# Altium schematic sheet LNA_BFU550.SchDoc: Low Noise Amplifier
size A4; Author: Almela; Revision: 1.2; SheetNumber: 5; SheetTotal: 7
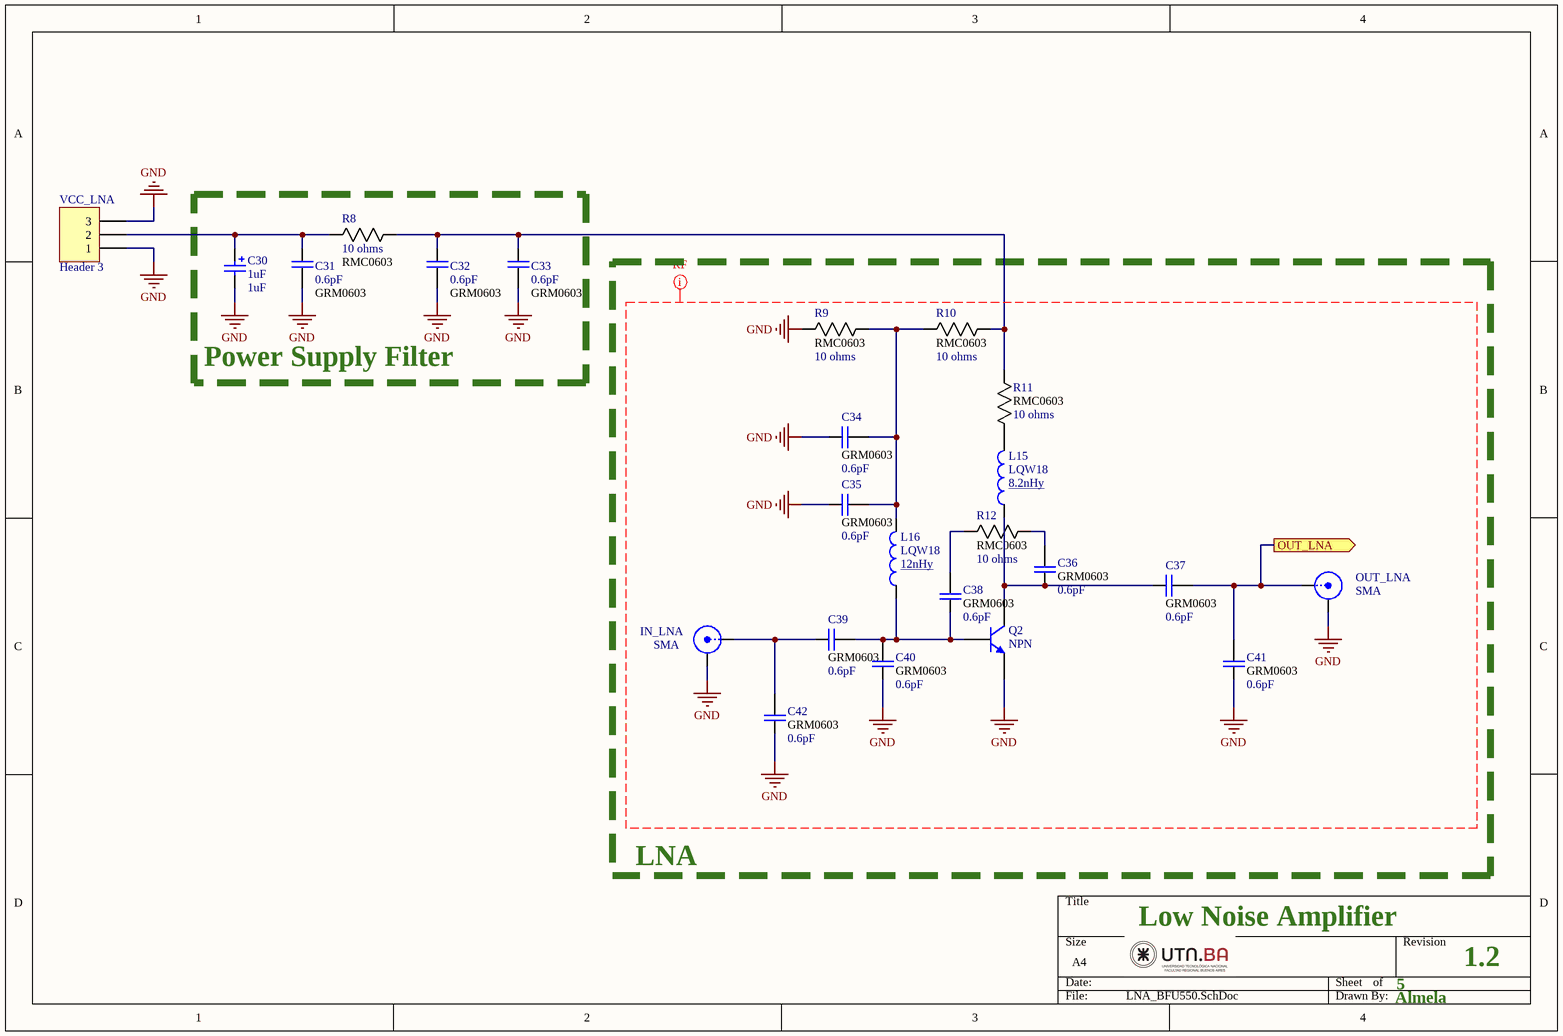
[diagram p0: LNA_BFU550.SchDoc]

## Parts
C30  1uF  [6-0805_N]
C31  value 0.6pF  footprint: GRM0603  [CAPC1608X90N]  (hidden comment: Cap 0603)
C32  value 0.6pF  footprint: GRM0603  [CAPC1608X90N]  (hidden comment: Cap 0603)
C33  value 0.6pF  footprint: GRM0603  [CAPC1608X90N]  (hidden comment: Cap 0603)
C34  value 0.6pF  footprint: GRM0603  [CAPC1608X90N]  (hidden comment: Cap 0603)
C35  value 0.6pF  footprint: GRM0603  [CAPC1608X90N]  (hidden comment: Cap 0603)
C36  value 0.6pF  footprint: GRM0603  [CAPC1608X90N]  (hidden comment: Cap 0603)
C37  value 0.6pF  footprint: GRM0603  [CAPC1608X90N]  (hidden comment: Cap 0603)
C38  value 0.6pF  footprint: GRM0603  [CAPC1608X90N]  (hidden comment: Cap 0603)
C39  value 0.6pF  footprint: GRM0603  [CAPC1608X90N]  (hidden comment: Cap 0603)
C40  value 0.6pF  footprint: GRM0603  [CAPC1608X90N]  (hidden comment: Cap 0603)
C41  value 0.6pF  footprint: GRM0603  [CAPC1608X90N]  (hidden comment: Cap 0603)
C42  value 0.6pF  footprint: GRM0603  [CAPC1608X90N]  (hidden comment: Cap 0603)
IN_LNA  SMA  [SMA-142-0701-851]
L15  LQW18  value 8.2nHy  [INDC1608X100N]
L16  LQW18  value 12nHy  [INDC1608X100N]
OUT_LNA  SMA  [SMA-142-0701-851]
Q2  NPN  [SOT23_N_bfu550a]
R8  value 10 ohms  footprint: RMC0603  [RESC1508X55N]  (hidden comment: Resistor)
R9  value 10 ohms  footprint: RMC0603  [RESC1508X55N]  (hidden comment: Resistor)
R10  value 10 ohms  footprint: RMC0603  [RESC1508X55N]  (hidden comment: Resistor)
R11  value 10 ohms  footprint: RMC0603  [RESC1508X55N]  (hidden comment: Resistor)
R12  value 10 ohms  footprint: RMC0603  [RESC1508X55N]  (hidden comment: Resistor)
VCC_LNA  Header 3  [HDR1X3]

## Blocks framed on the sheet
Power Supply Filter: C30-C33 R8

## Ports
OUT_LNA (out)

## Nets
GND: C30.2 C31.2 C32.2 C33.2 C34.1 C35.1 C40.1 C41.1 C42.1 IN_LNA.2(Y) OUT_LNA.2(Y) Q2.2(E) R9.2 VCC_LNA.1 VCC_LNA.3
OUT_LNA: C37.2 C41.2 OUT_LNA.1(X) ; port OUT_LNA
NetC30_1: C30.1 C31.1 R8.2 VCC_LNA.2
NetC32_1: C32.1 C33.1 R8.1 R10.2 R11.2
NetC34_2: C34.2 C35.2 L16.2 R9.1 R10.1
NetC36_1: C36.1 C37.1 L15.1 Q2.3(C)
NetC36_2: C36.2 R12.2
NetC38_1: C38.1 C39.2 C40.2 L16.1 Q2.1(B)
NetC38_2: C38.2 R12.1
NetC39_1: C39.1 C42.2 IN_LNA.1(X)
NetL15_2: L15.2 R11.1

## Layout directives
net class RF50R: GND

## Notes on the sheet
- LNA

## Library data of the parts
C30 = Cap Pol2_1: Polarized Capacitor (Axial)
C31-C42 = Cap: Capacitor GRM18 0603
IN_LNA OUT_LNA = SMB: SMB Straight Connector
L15 L16 = LQW18_1: Inductor LQW Package: 0603 (1608); MP: LQW18ANR47J00D; MF: Murata
Q2 = BFU550A: NPN Bipolar Transistor
R8-R12 = Resistor: Resistor RMC0603; Mfr_Name: Stackpole International
VCC_LNA = Header 3: Header, 3-Pin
